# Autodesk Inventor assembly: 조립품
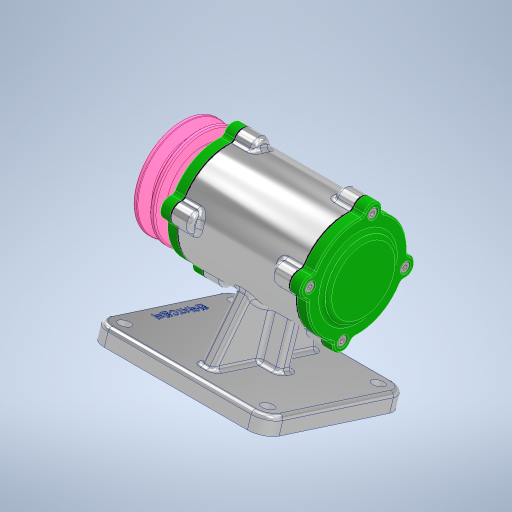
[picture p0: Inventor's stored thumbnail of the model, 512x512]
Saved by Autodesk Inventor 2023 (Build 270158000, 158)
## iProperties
Created: 2023-08
Part Number: 조립품
Document SubType Name: Assembly
Designer: asung
Author: asung
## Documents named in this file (12)
- C:\Users\asung\Desktop\730808V1013\조립품.iam
- C:\Users\asung\Desktop\730808V1013\본체.ipt
- C:\Users\asung\Desktop\730808V1013\베어링 6204.ipt
- C:\Users\asung\Desktop\730808V1013\개스킷.ipt
- C:\Users\asung\Desktop\730808V1013\뒤커버.ipt
- C:\Users\asung\Desktop\730808V1013\앞커버.ipt
- C:\Users\asung\Desktop\730808V1013\볼트 M4 x 12.ipt
- C:\Users\asung\Desktop\730808V1013\축.ipt
- C:\Users\asung\Desktop\730808V1013\키 4 x 4.ipt
- C:\Users\asung\Desktop\730808V1013\V-벨트풀리.ipt
- C:\Users\asung\Desktop\730808V1013\너트 M12 x 1.25.ipt
- C:\Users\asung\Desktop\730808V1013\오일 실.ipt
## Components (8 placed, 6 different names)
1. KS B 2023 6204 - 20 x 47 x 14:1
2. KS B 2023 6204 - 20 x 47 x 14:2
3. 개스킷:1
4. 개스킷:2
5. KS B 1311 (I) 4 x 4 x 12:1
6. V-벨트풀리:1
7. KS B 1012 클래스 1 일반 - 미터 M12x1.25:1
8. KS B 2804 D D - 20 32 8:1
